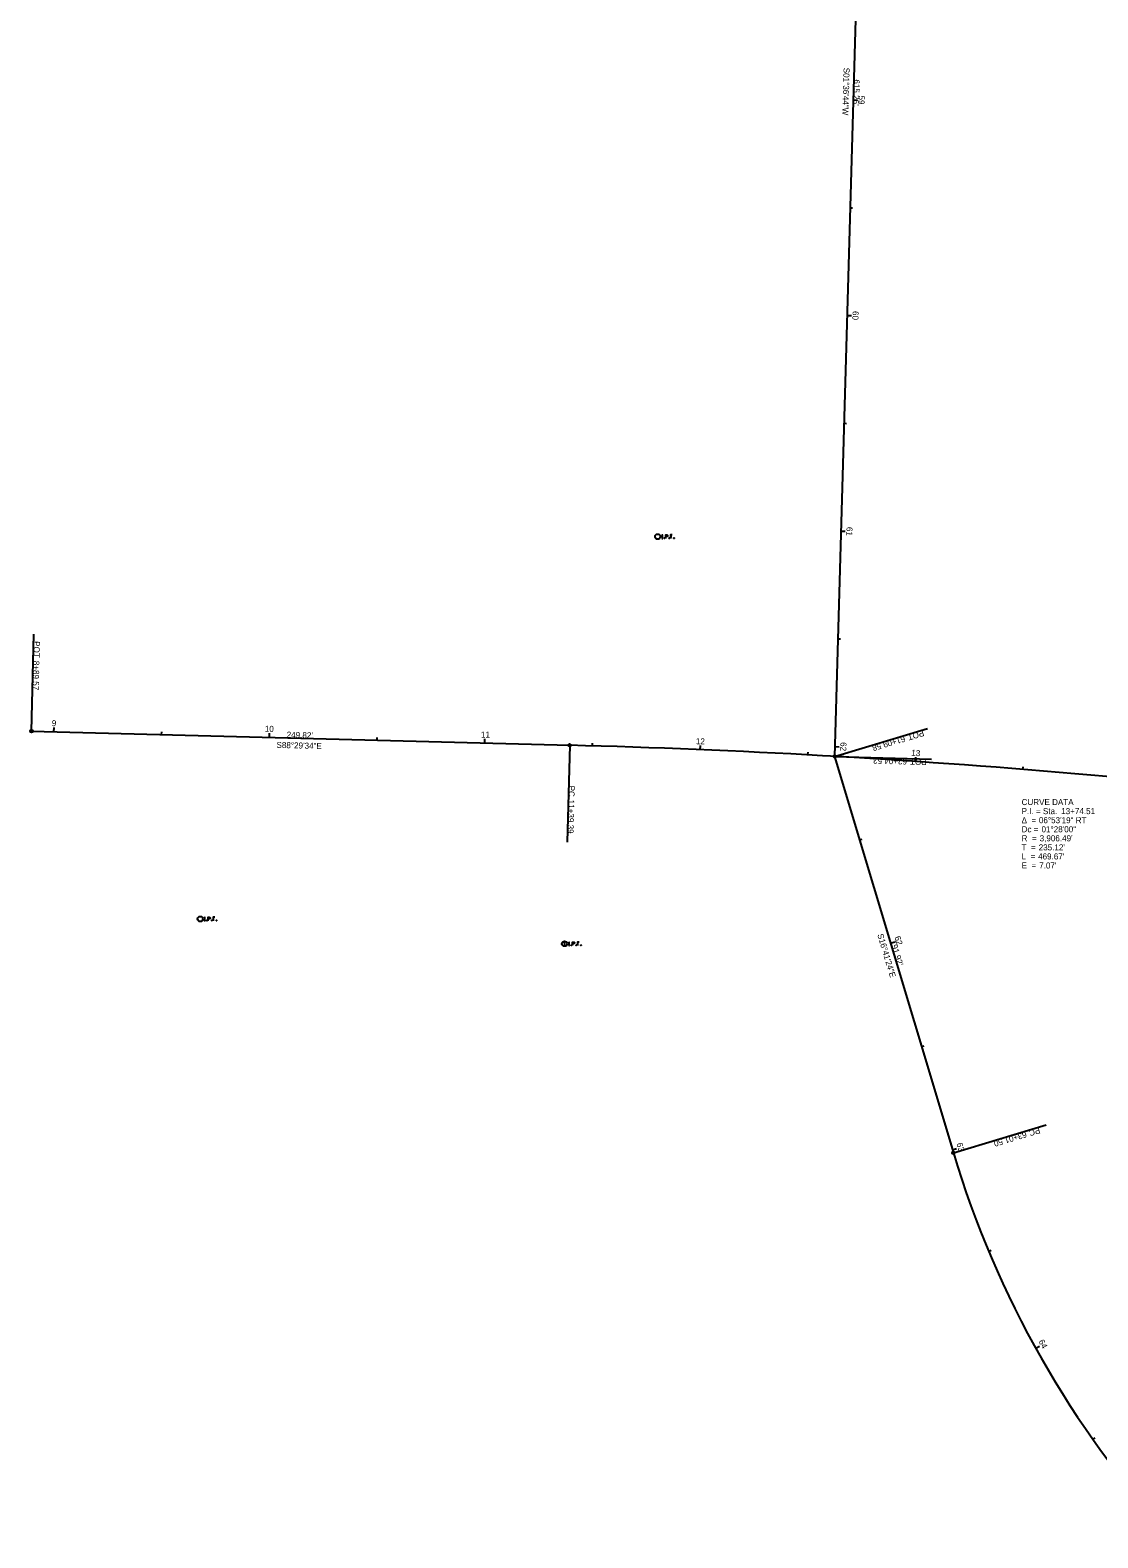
# Model space of a CAD drawing. Extents: x 1918148 to 1920349, y 624677 to 627727.
# Drawn here: x 1918496 to 1918991, y 625509 to 626208 of the extents above; entities that cross this region are included whole.
import ezdxf

# ---------------------------------------------------------------- set-up
doc = ezdxf.new("R2010")
doc.units = 0
for name, color, linetype in [('_CIVIL_CONSTRUCTION', 7, 'Continuous'), ('RS_Raster1', 7, 'Continuous'), ('RW_X_CL', 7, 'Continuous'), ('RW_X_CL_100_Bearings', 7, 'Continuous'), ('RW_X_CL_100_Cardinal_Points', 7, 'Continuous'), ('RW_X_CL_100_Curve_Data', 7, 'Continuous'), ('SV_X_Mon_Cells_Found', 7, 'Continuous')]:
    doc.layers.add(name, color=color, linetype=linetype)

msp = doc.modelspace()

# ---------------------------------------------------------------- linework, layer by layer
at = {"layer": 'RS_Raster1'}
for p, q in [((1918886.1, 626486.21), (1918868.79, 625871.19)), ((1918496.14, 625882.93), (1918745.88, 625876.36)), ((1918868.79, 625871.19), (1918923.91, 625687.36))]:
    msp.add_line(p, q, dxfattribs=at)
for centre, radius, start, end in [((1918643.12, 621971.22), 3906.49, 81.60417, 88.49278), ((1919362.98, 625819), 458.38, 196.69, 222.58667)]:
    msp.add_arc(centre, radius, start, end, dxfattribs=at)
at = {"layer": 'RW_X_CL'}
for p, q in [((1918496.14, 625882.93), (1918497.33, 625927.92)), ((1918868.79, 625871.19), (1918911.9, 625884.11)), ((1918745.88, 625876.36), (1918744.69, 625831.38)), ((1918868.79, 625871.19), (1918913.77, 625869.93)), ((1918923.91, 625687.36), (1918967.02, 625700.28))]:
    msp.add_line(p, q, dxfattribs=at)
for centre in [(1918496.14, 625882.93), (1918745.88, 625876.36), (1918868.79, 625871.19), (1918868.79, 625871.19), (1918923.91, 625687.36)]:
    msp.add_circle(centre, 0.6, dxfattribs=at)
at = {"layer": 'RW_X_CL_100_Cardinal_Points'}
for p, q in [((1918877.36, 626175.6), (1918879.36, 626175.55)), ((1918875.95, 626125.62), (1918877.15, 626125.59)), ((1918874.55, 626075.64), (1918876.55, 626075.59)), ((1918873.14, 626025.66), (1918874.34, 626025.63)), ((1918871.73, 625975.68), (1918873.73, 625975.63)), ((1918870.33, 625925.7), (1918871.53, 625925.67)), ((1918506.57, 625882.66), (1918506.62, 625884.66)), ((1918556.55, 625881.34), (1918556.58, 625882.54)), ((1918606.53, 625880.03), (1918606.59, 625882.03)), ((1918656.52, 625878.71), (1918656.55, 625879.91)), ((1918706.5, 625877.4), (1918706.55, 625879.4)), ((1918756.48, 625876.07), (1918756.52, 625877.27)), ((1918806.45, 625874.3), (1918806.53, 625876.3)), ((1918868.92, 625875.72), (1918870.92, 625875.67)), ((1918856.39, 625871.89), (1918856.46, 625873.09)), ((1918906.3, 625868.84), (1918906.43, 625870.84)), ((1918956.16, 625865.15), (1918956.26, 625866.35)), ((1918880.4, 625832.47), (1918881.55, 625832.82)), ((1918894.76, 625784.58), (1918896.68, 625785.15)), ((1918909.12, 625736.69), (1918910.27, 625737.03)), ((1918923.48, 625688.79), (1918925.4, 625689.37)), ((1918940.27, 625641.72), (1918941.38, 625642.19)), ((1918962.08, 625596.76), (1918963.83, 625597.73)), ((1918988.66, 625554.44), (1918989.64, 625555.13))]:
    msp.add_line(p, q, dxfattribs=at)
at = {"layer": 'SV_X_Mon_Cells_Found'}
msp.add_line((1918743.48, 625784.44), (1918743.48, 625783.56), dxfattribs=at)
for points in [[(1918788.7, 625973.91), (1918789.05, 625973.91)], [(1918788.88, 625972.31), (1918788.88, 625973.91)], [(1918790.44, 625972.31), (1918790.44, 625973.91), (1918790.97, 625973.91), (1918791.03, 625973.9), (1918791.1, 625973.87), (1918791.14, 625973.85), (1918791.17, 625973.82), (1918791.21, 625973.76), (1918791.25, 625973.7), (1918791.27, 625973.6), (1918791.27, 625973.45), (1918791.26, 625973.4), (1918791.24, 625973.32), (1918791.19, 625973.23), (1918791.15, 625973.19), (1918791.11, 625973.17), (1918791.06, 625973.14), (1918790.97, 625973.13), (1918790.44, 625973.13)], [(1918793.45, 625973.91), (1918792.69, 625973.91), (1918792.69, 625972.31)], [(1918788.7, 625972.31), (1918789.05, 625972.31)], [(1918789.84, 625972.53), (1918789.89, 625972.53), (1918789.92, 625972.5), (1918789.96, 625972.45), (1918789.96, 625972.39), (1918789.92, 625972.34), (1918789.89, 625972.31), (1918789.84, 625972.31), (1918789.8, 625972.34), (1918789.77, 625972.39), (1918789.77, 625972.45), (1918789.8, 625972.5), (1918789.84, 625972.53)], [(1918792.08, 625972.53), (1918792.14, 625972.53), (1918792.17, 625972.5), (1918792.21, 625972.45), (1918792.21, 625972.39), (1918792.17, 625972.34), (1918792.14, 625972.31), (1918792.08, 625972.31), (1918792.05, 625972.34), (1918792.02, 625972.39), (1918792.02, 625972.45), (1918792.05, 625972.5), (1918792.08, 625972.53)], [(1918792.69, 625973.13), (1918793.23, 625973.13)], [(1918794.23, 625972.53), (1918794.29, 625972.53), (1918794.32, 625972.5), (1918794.36, 625972.45), (1918794.36, 625972.39), (1918794.32, 625972.34), (1918794.29, 625972.31), (1918794.23, 625972.31), (1918794.2, 625972.34), (1918794.17, 625972.39), (1918794.17, 625972.45), (1918794.2, 625972.5), (1918794.23, 625972.53)], [(1918576.45, 625796.6), (1918576.81, 625796.6)], [(1918576.45, 625795), (1918576.81, 625795)], [(1918576.63, 625795), (1918576.63, 625796.6)], [(1918577.59, 625795.21), (1918577.64, 625795.21), (1918577.68, 625795.19), (1918577.71, 625795.14), (1918577.71, 625795.08), (1918577.68, 625795.03), (1918577.64, 625795), (1918577.59, 625795), (1918577.55, 625795.03), (1918577.52, 625795.08), (1918577.52, 625795.14), (1918577.55, 625795.19), (1918577.59, 625795.21)], [(1918578.19, 625795), (1918578.19, 625796.6), (1918578.72, 625796.6), (1918578.78, 625796.59), (1918578.86, 625796.56), (1918578.89, 625796.54), (1918578.92, 625796.51), (1918578.97, 625796.45), (1918579, 625796.39), (1918579.02, 625796.28), (1918579.02, 625796.13), (1918579.01, 625796.08), (1918578.99, 625796.01), (1918578.94, 625795.92), (1918578.9, 625795.88), (1918578.87, 625795.86), (1918578.81, 625795.83), (1918578.72, 625795.82), (1918578.19, 625795.82)], [(1918579.84, 625795.21), (1918579.89, 625795.21), (1918579.92, 625795.19), (1918579.96, 625795.14), (1918579.96, 625795.08), (1918579.92, 625795.03), (1918579.89, 625795), (1918579.84, 625795), (1918579.8, 625795.03), (1918579.77, 625795.08), (1918579.77, 625795.14), (1918579.8, 625795.19), (1918579.84, 625795.21)], [(1918581.2, 625796.6), (1918580.44, 625796.6), (1918580.44, 625795)], [(1918580.44, 625795.82), (1918580.98, 625795.82)], [(1918581.99, 625795.21), (1918582.04, 625795.21), (1918582.07, 625795.19), (1918582.11, 625795.14), (1918582.11, 625795.08), (1918582.07, 625795.03), (1918582.04, 625795), (1918581.99, 625795), (1918581.95, 625795.03), (1918581.92, 625795.08), (1918581.92, 625795.14), (1918581.95, 625795.19), (1918581.99, 625795.21)], [(1918745.51, 625785.12), (1918745.86, 625785.12)], [(1918745.69, 625783.52), (1918745.69, 625785.12)], [(1918747.25, 625783.52), (1918747.25, 625785.12), (1918747.78, 625785.12), (1918747.84, 625785.11), (1918747.91, 625785.09), (1918747.95, 625785.06), (1918747.98, 625785.04), (1918748.02, 625784.97), (1918748.06, 625784.91), (1918748.08, 625784.81), (1918748.08, 625784.66), (1918748.07, 625784.61), (1918748.04, 625784.53), (1918748, 625784.44), (1918747.96, 625784.41), (1918747.92, 625784.38), (1918747.87, 625784.36), (1918747.78, 625784.34), (1918747.25, 625784.34)], [(1918750.26, 625785.12), (1918749.5, 625785.12), (1918749.5, 625783.52)], [(1918745.51, 625783.52), (1918745.86, 625783.52)], [(1918746.64, 625783.74), (1918746.7, 625783.74), (1918746.73, 625783.71), (1918746.77, 625783.66), (1918746.77, 625783.6), (1918746.73, 625783.55), (1918746.7, 625783.52), (1918746.64, 625783.52), (1918746.61, 625783.55), (1918746.58, 625783.6), (1918746.58, 625783.66), (1918746.61, 625783.71), (1918746.64, 625783.74)], [(1918748.89, 625783.74), (1918748.95, 625783.74), (1918748.98, 625783.71), (1918749.01, 625783.66), (1918749.01, 625783.6), (1918748.98, 625783.55), (1918748.95, 625783.52), (1918748.89, 625783.52), (1918748.86, 625783.55), (1918748.83, 625783.6), (1918748.83, 625783.66), (1918748.86, 625783.71), (1918748.89, 625783.74)], [(1918749.5, 625784.34), (1918750.04, 625784.34)], [(1918751.04, 625783.74), (1918751.1, 625783.74), (1918751.13, 625783.71), (1918751.16, 625783.66), (1918751.16, 625783.6), (1918751.13, 625783.55), (1918751.1, 625783.52), (1918751.04, 625783.52), (1918751.01, 625783.55), (1918750.98, 625783.6), (1918750.98, 625783.66), (1918751.01, 625783.71), (1918751.04, 625783.74)]]:
    msp.add_lwpolyline(points, dxfattribs=at)
for centre, radius in [((1918786.69, 625973.11), 1.2), ((1918574.44, 625795.8), 1.2), ((1918743.48, 625784.32), 1.2), ((1918743.48, 625784.98), 0.16)]:
    msp.add_circle(centre, radius, dxfattribs=at)

# ---------------------------------------------------------------- texts
at = {"layer": '_CIVIL_CONSTRUCTION'}
for s, rotation, p in [('S01°36\'44"W', 268.38778, (1918872.98, 626190.59)), ('S88°29\'34"E', 358.49278, (1918609.81, 625875.14)), ('S16°41\'24"E', 286.69, (1918888.57, 625788.5))]:
    msp.add_text(s, height=2.8, rotation=rotation, dxfattribs=at).set_placement(p)
at = {"layer": 'RW_X_CL'}
for s, rotation, p in [('POT', 268.49278, (1918497.29, 625924.68)), ('8+89.57', 268.49278, (1918497.05, 625915.56)), ('POT', 196.69, (1918909.79, 625883.44)), ('61+09.58', 196.69, (1918901.05, 625880.81)), ('62+04.53', 178.38778, (1918902.42, 625870.2)), ('POT', 178.38778, (1918911.55, 625869.94)), ('PC', 268.49278, (1918745.43, 625857.68)), ('11+39.39', 268.49278, (1918745.26, 625851.16)), ('63+01.50', 196.69, (1918957.42, 625697.35)), ('PC', 196.69, (1918963.66, 625699.23))]:
    msp.add_text(s, height=2.8, rotation=rotation, dxfattribs=at).set_placement(p)
at = {"layer": 'RW_X_CL_100_Bearings'}
for s, p in [('CURVE DATA', (1918955.55, 625848.61)), ('Δ  = ', (1918955.55, 625840.21)), ('P.I. = Sta. ', (1918955.55, 625844.41)), ('06°53\'19" RT', (1918963.57, 625840.21)), ('13+74.51', (1918973.92, 625844.41)), ('Dc = ', (1918955.55, 625836.01)), ('R  = ', (1918955.55, 625831.81)), ("3,906.49'", (1918963.92, 625831.81)), ('01°28\'00"', (1918964.79, 625836.01)), ('T  = ', (1918955.55, 625827.61)), ("235.12'", (1918963.48, 625827.61)), ('L  = ', (1918955.55, 625823.41)), ('E  = ', (1918955.55, 625819.21)), ("469.67'", (1918963.2, 625823.41)), ("7.07'", (1918963.7, 625819.21))]:
    msp.add_text(s, height=2.8, dxfattribs=at).set_placement(p)
at = {"layer": 'RW_X_CL_100_Cardinal_Points'}
for s, rotation, p in [('59', 268.38778, (1918879.97, 626177.7)), ('60', 268.38778, (1918877.15, 626077.76)), ('61', 268.38778, (1918874.34, 625977.63)), ('9', 358.49278, (1918505.56, 625885.23)), ('10', 358.49278, (1918604.41, 625882.63)), ('11', 358.49278, (1918704.69, 625879.95)), ('12', 357.60382, (1918804.37, 625876.89)), ('62', 268.38778, (1918871.53, 625877.84)), ('13', 356.13714, (1918904.3, 625871.53)), ('62', 286.69, (1918896.57, 625787.41)), ('63', 286.69, (1918925.29, 625691.61)), ('64', 299.00214, (1918963.27, 625599.87))]:
    msp.add_text(s, height=2.8, rotation=rotation, dxfattribs=at).set_placement(p)
at = {"layer": 'RW_X_CL_100_Curve_Data'}
for s, rotation, p in [("615.26'", 268.38778, (1918877.68, 626185.18)), ("249.82'", 358.49278, (1918614.53, 625879.87)), ("191.92'", 286.69, (1918894.53, 625785.5))]:
    msp.add_text(s, height=2.8, rotation=rotation, dxfattribs=at).set_placement(p)

doc.saveas('drawing.dxf')
